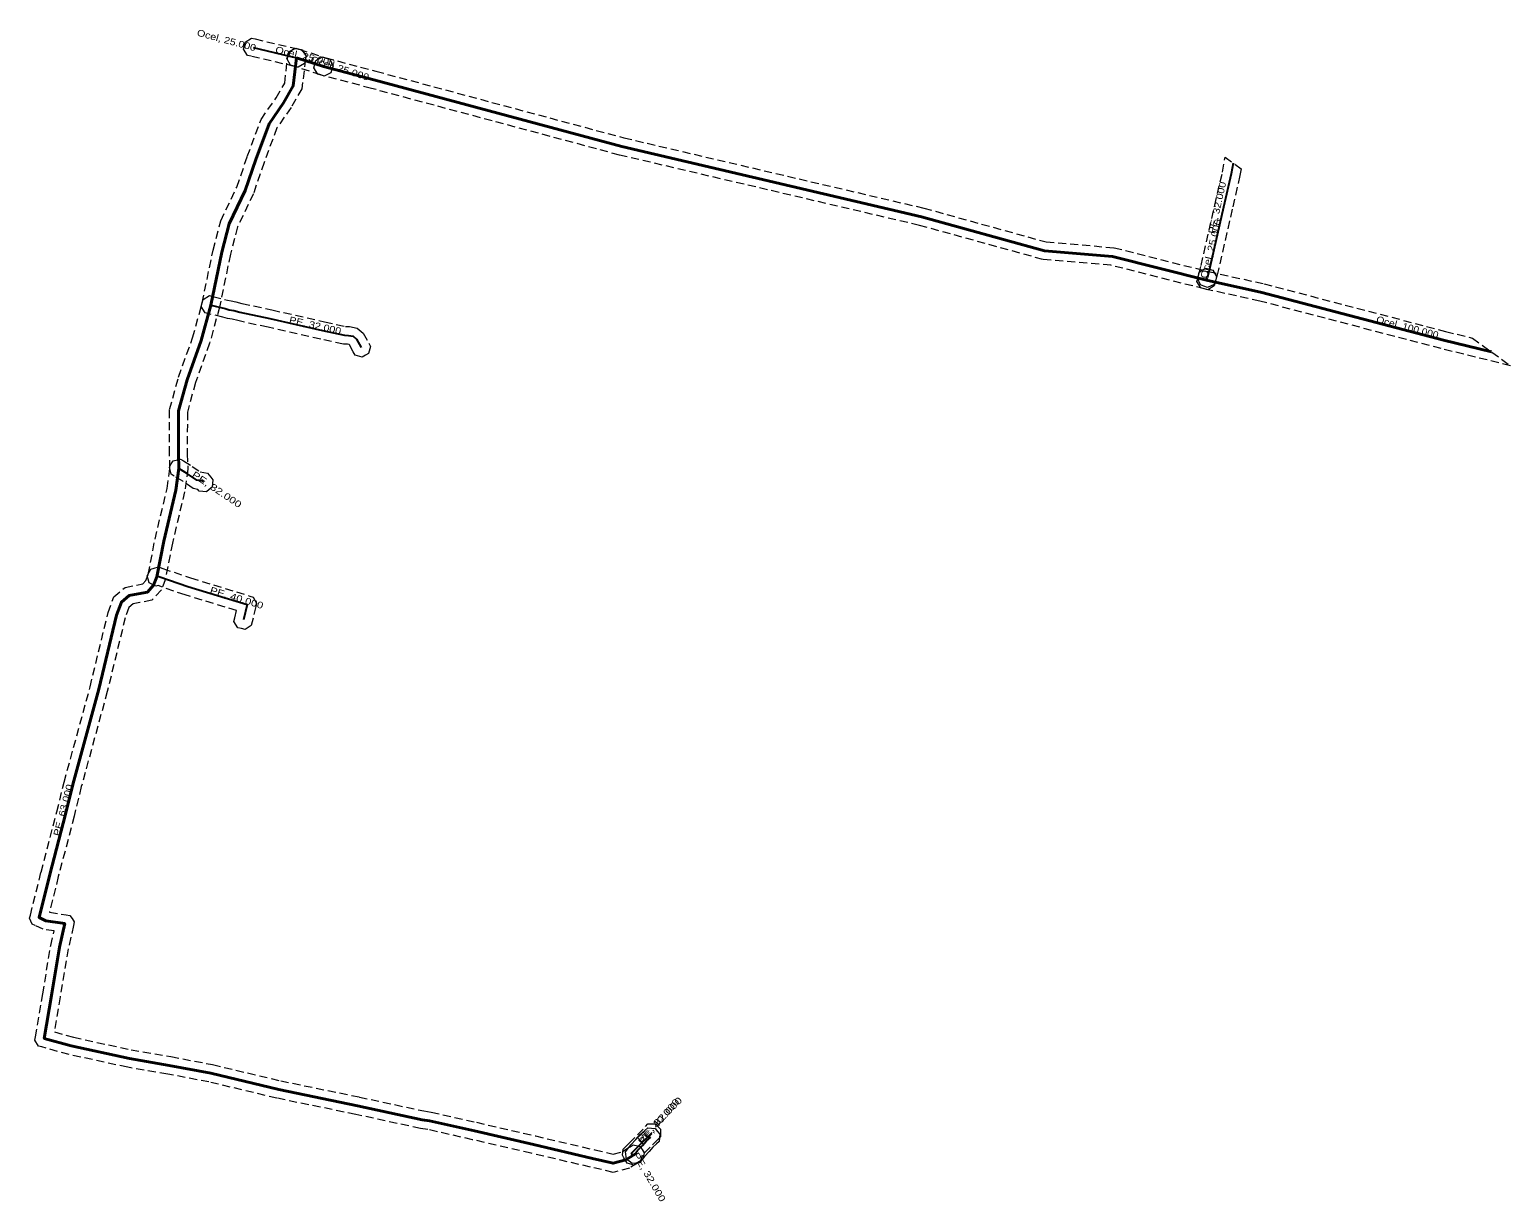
# Model space of a CAD drawing. Extents: x -640775 to -624586, y -1148563 to -1138811.
# Drawn here: x -625900 to -625733.5, y -1147350.6 to -1147218.8 of the extents above; entities that cross this region are included whole.
import ezdxf
from ezdxf.enums import TextEntityAlignment as Align

# ---------------------------------------------------------------- set-up
doc = ezdxf.new("R2010")
doc.units = 0
doc.header["$LTSCALE"] = 0.3
doc.linetypes.add('MEDIUM_DASHED', pattern=[4.5, 3, -1.5])
doc.layers.add('1', color=7, linetype='MEDIUM_DASHED', lineweight=13)
doc.layers.add('24', color=7, linetype='Continuous', lineweight=40)
doc.layers.add('30', color=7, linetype='Continuous')

msp = doc.modelspace()

# ---------------------------------------------------------------- linework, layer by layer
at = {"layer": '1'}
for points in [[(-625875.72, -1147220.24), (-625875.016, -1147219.802), (-625874.613, -1147219.896), (-625869.723, -1147221.036), (-625869.32, -1147221.13), (-625868.882, -1147221.834), (-625868.976, -1147222.237), (-625869.07, -1147222.64), (-625869.774, -1147223.078), (-625870.177, -1147222.984), (-625875.067, -1147221.844), (-625875.47, -1147221.75), (-625875.908, -1147221.046), (-625875.814, -1147220.643)], [(-625870.774, -1147221.308), (-625870.036, -1147220.931), (-625869.642, -1147221.059), (-625866.612, -1147222.039), (-625866.218, -1147222.166), (-625865.841, -1147222.904), (-625865.969, -1147223.298), (-625866.096, -1147223.692), (-625866.834, -1147224.069), (-625867.228, -1147223.941), (-625870.258, -1147222.961), (-625870.652, -1147222.834), (-625871.029, -1147222.096), (-625870.901, -1147221.702)], [(-625740.763, -1147252.771), (-625737.736, -1147253.519), (-625733.477, -1147256.63), (-625741.257, -1147254.709), (-625761.644, -1147249.362), (-625767.88, -1147247.993), (-625778.376, -1147245.339), (-625786.027, -1147244.689), (-625799.927, -1147240.849), (-625833.634, -1147232.95), (-625861.538, -1147225.456), (-625867.177, -1147223.956), (-625867.577, -1147223.85), (-625867.992, -1147223.133), (-625867.886, -1147222.733), (-625867.78, -1147222.333), (-625867.063, -1147221.918), (-625866.663, -1147222.024), (-625861.022, -1147223.524), (-625833.146, -1147231.01), (-625799.433, -1147238.911), (-625785.673, -1147242.711), (-625778.044, -1147243.361), (-625767.42, -1147246.047), (-625761.176, -1147247.418)], [(-625765.85, -1147234.861), (-625765.555, -1147233.189), (-625763.756, -1147234.503), (-625763.89, -1147235.259), (-625764.755, -1147239.033), (-625766.298, -1147245.827), (-625766.596, -1147246.963), (-625766.644, -1147247.091), (-625766.789, -1147247.479), (-625767.543, -1147247.821), (-625767.931, -1147247.676), (-625768.319, -1147247.531), (-625768.661, -1147246.777), (-625768.516, -1147246.389), (-625768.504, -1147246.357), (-625768.242, -1147245.353), (-625766.705, -1147238.587)], [(-625768.295, -1147247.89), (-625768.721, -1147247.179), (-625768.62, -1147246.777), (-625768.55, -1147246.497), (-625768.45, -1147246.095), (-625767.739, -1147245.669), (-625767.337, -1147245.77), (-625766.935, -1147245.87), (-625766.509, -1147246.581), (-625766.61, -1147246.983), (-625766.68, -1147247.263), (-625766.78, -1147247.665), (-625767.491, -1147248.091), (-625767.893, -1147247.99)], [(-625880.46, -1147249.167), (-625879.751, -1147248.74), (-625879.349, -1147248.84), (-625877.733, -1147249.241), (-625877.31, -1147249.351), (-625876.781, -1147249.441), (-625876.099, -1147249.617), (-625872.723, -1147250.354), (-625866.802, -1147251.694), (-625864.451, -1147252.212), (-625863.99, -1147252.222), (-625863.154, -1147252.389), (-625862.447, -1147252.982), (-625861.827, -1147254.093), (-625861.625, -1147254.455), (-625861.851, -1147255.251), (-625862.213, -1147255.453), (-625862.575, -1147255.655), (-625863.371, -1147255.429), (-625863.573, -1147255.067), (-625864.013, -1147254.278), (-625864.046, -1147254.251), (-625864.21, -1147254.218), (-625864.689, -1147254.208), (-625867.238, -1147253.646), (-625873.157, -1147252.306), (-625876.561, -1147251.563), (-625877.199, -1147251.399), (-625877.73, -1147251.309), (-625878.227, -1147251.179), (-625879.831, -1147250.78), (-625880.233, -1147250.68), (-625880.66, -1147249.971), (-625880.56, -1147249.569)], [(-625880.089, -1147270.81), (-625880.912, -1147270.719), (-625881.068, -1147270.524), (-625881.567, -1147270.418), (-625882.749, -1147269.622), (-625883.7, -1147269.044), (-625884.054, -1147268.829), (-625884.249, -1147268.024), (-625884.034, -1147267.67), (-625883.819, -1147267.316), (-625883.014, -1147267.121), (-625882.66, -1147267.336), (-625881.671, -1147267.938), (-625880.773, -1147268.542), (-625879.953, -1147268.716), (-625879.609, -1147269.145), (-625879.35, -1147269.469), (-625879.441, -1147270.292), (-625879.765, -1147270.551)], [(-625876.7, -1147284.153), (-625882.478, -1147282.392), (-625885.527, -1147281.35), (-625885.785, -1147281.426), (-625886.512, -1147281.03), (-625886.629, -1147280.632), (-625886.746, -1147280.235), (-625886.35, -1147279.508), (-625885.952, -1147279.391), (-625885.472, -1147279.249), (-625885.002, -1147279.415), (-625881.862, -1147280.488), (-625875.218, -1147282.513), (-625874.839, -1147282.629), (-625874.446, -1147283.316), (-625874.537, -1147283.701), (-625874.947, -1147285.431), (-625875.043, -1147285.834), (-625875.748, -1147286.269), (-625876.151, -1147286.173), (-625876.554, -1147286.077), (-625876.989, -1147285.372), (-625876.893, -1147284.969)], [(-625829.309, -1147343.563), (-625830.207, -1147344.471), (-625831.102, -1147345.385), (-625831.278, -1147346.055), (-625831.636, -1147346.264), (-625831.994, -1147346.473), (-625832.795, -1147346.262), (-625833.004, -1147345.904), (-625833.074, -1147345.784), (-625833.144, -1147345.664), (-625833.314, -1147345.372), (-625833.231, -1147344.702), (-625832.995, -1147344.461), (-625832.555, -1147344.011), (-625831.633, -1147343.069), (-625830.731, -1147342.157), (-625830.44, -1147341.862), (-625829.612, -1147341.858), (-625829.317, -1147342.149), (-625829.022, -1147342.44), (-625829.018, -1147343.268)], [(-625832.872, -1147345.803), (-625832.973, -1147344.981), (-625832.718, -1147344.655), (-625832.371, -1147344.21), (-625831.804, -1147343.602), (-625831.317, -1147343.039), (-625830.779, -1147342.58), (-625830.464, -1147342.311), (-625829.639, -1147342.376), (-625829.37, -1147342.691), (-625829.101, -1147343.006), (-625829.166, -1147343.831), (-625829.481, -1147344.1), (-625829.903, -1147344.461), (-625830.316, -1147344.938), (-625830.849, -1147345.51), (-625831.142, -1147345.885), (-625831.397, -1147346.212), (-625832.219, -1147346.313), (-625832.545, -1147346.058)]]:
    msp.add_lwpolyline(points, close=True, dxfattribs=at)
for points in [[(-625894.96, -1147307.265), (-625896.741, -1147314.057), (-625897.736, -1147318.062), (-625895.867, -1147318.352), (-625895.44, -1147318.418), (-625895.195, -1147318.775), (-625894.951, -1147319.131), (-625895.043, -1147319.554), (-625895.618, -1147322.18), (-625896.524, -1147327.575), (-625897.185, -1147331.519), (-625895.04, -1147332.119), (-625888.56, -1147333.518), (-625884.082, -1147334.286), (-625879.39, -1147335.182), (-625871.723, -1147337.014), (-625862.884, -1147338.832), (-625855.647, -1147340.397), (-625854.813, -1147340.527), (-625849.717, -1147341.675), (-625843.103, -1147343.206), (-625836.434, -1147344.766), (-625834.373, -1147345.241), (-625833.324, -1147344.971), (-625832.673, -1147344.554), (-625832.456, -1147344.42), (-625832.104, -1147344.202), (-625831.298, -1147344.392), (-625831.08, -1147344.744), (-625830.862, -1147345.096), (-625831.052, -1147345.902), (-625831.404, -1147346.12), (-625831.607, -1147346.246), (-625832.516, -1147346.829), (-625834.347, -1147347.299), (-625836.886, -1147346.714), (-625843.557, -1147345.154), (-625850.163, -1147343.625), (-625855.187, -1147342.493), (-625856.013, -1147342.363), (-625863.296, -1147340.788), (-625872.157, -1147338.966), (-625879.81, -1147337.138), (-625884.438, -1147336.254), (-625888.94, -1147335.482), (-625895.52, -1147334.061), (-625898.589, -1147333.203), (-625898.958, -1147333.1), (-625899.37, -1147332.453), (-625899.306, -1147332.075), (-625898.496, -1147327.245), (-625897.582, -1147321.8), (-625897.224, -1147320.165), (-625898.452, -1147319.975), (-625899.348, -1147319.539), (-625899.666, -1147319.384), (-625899.966, -1147318.743), (-625899.88, -1147318.399), (-625898.679, -1147313.563), (-625896.9, -1147306.775), (-625896.088, -1147303.44), (-625893.168, -1147292.74), (-625891.139, -1147284.382), (-625890.5, -1147282.61), (-625889.238, -1147281.539), (-625887.961, -1147281.288), (-625887.242, -1147281.15), (-625886.89, -1147280.768), (-625886.636, -1147280.08), (-625885.868, -1147276.138), (-625884.504, -1147270.424), (-625884.183, -1147268.138), (-625884.24, -1147266.557), (-625884.23, -1147261.564), (-625883.224, -1147257.908), (-625881.634, -1147253.488), (-625880.563, -1147249.577), (-625879.344, -1147243.632), (-625878.473, -1147240.333), (-625876.658, -1147236.542), (-625875.492, -1147233.115), (-625873.943, -1147228.953), (-625872.255, -1147226.524), (-625871.289, -1147224.849), (-625870.943, -1147221.894), (-625870.895, -1147221.482), (-625870.245, -1147220.969), (-625869.834, -1147221.017), (-625869.422, -1147221.065), (-625868.909, -1147221.715), (-625868.957, -1147222.126), (-625869.351, -1147225.491), (-625870.565, -1147227.596), (-625872.157, -1147229.887), (-625873.608, -1147233.785), (-625874.802, -1147237.298), (-625876.587, -1147241.027), (-625877.396, -1147244.088), (-625878.617, -1147250.043), (-625879.726, -1147254.092), (-625881.316, -1147258.512)], [(-625881.316, -1147258.512), (-625882.23, -1147261.836), (-625882.24, -1147266.523), (-625882.177, -1147268.242), (-625882.536, -1147270.796), (-625883.912, -1147276.562), (-625884.704, -1147280.62), (-625885.15, -1147281.832), (-625886.218, -1147282.99), (-625887.579, -1147283.252), (-625888.342, -1147283.401), (-625888.8, -1147283.79), (-625889.221, -1147284.958), (-625891.232, -1147293.24), (-625894.152, -1147303.94), (-625894.96, -1147307.265)]]:
    msp.add_lwpolyline(points, dxfattribs=at)
at = {"layer": '24', "lineweight": 25}
for p, q in [((-625874.84, -1147220.87), (-625869.95, -1147222.01)), ((-625767.65, -1147247.02), (-625767.58, -1147246.74))]:
    msp.add_line(p, q, dxfattribs=at)
at = {"layer": '24'}
msp.add_line((-625869.95, -1147222.01), (-625866.92, -1147222.99), dxfattribs=at)
for points in [[(-625869.95, -1147222.01), (-625870.32, -1147225.17), (-625871.41, -1147227.06), (-625873.05, -1147229.42), (-625874.55, -1147233.45), (-625875.73, -1147236.92), (-625877.53, -1147240.68), (-625878.37, -1147243.86), (-625879.59, -1147249.81)], [(-625866.92, -1147222.99), (-625861.28, -1147224.49), (-625833.39, -1147231.98), (-625799.68, -1147239.88), (-625785.85, -1147243.7), (-625778.21, -1147244.35), (-625767.65, -1147247.02)], [(-625767.65, -1147247.02), (-625761.41, -1147248.39), (-625741.01, -1147253.74), (-625735.608, -1147255.074)], [(-625879.59, -1147249.81), (-625880.68, -1147253.79), (-625882.27, -1147258.21), (-625883.23, -1147261.7), (-625883.24, -1147266.54), (-625883.18, -1147268.19)], [(-625883.18, -1147268.19), (-625883.52, -1147270.61), (-625884.89, -1147276.35), (-625885.67, -1147280.35)], [(-625885.67, -1147280.35), (-625886.02, -1147281.3), (-625886.73, -1147282.07), (-625887.77, -1147282.27), (-625888.79, -1147282.47), (-625889.65, -1147283.2), (-625890.18, -1147284.67), (-625892.2, -1147292.99), (-625895.12, -1147303.69), (-625895.93, -1147307.02), (-625897.71, -1147313.81), (-625898.91, -1147318.64), (-625898.15, -1147319.01), (-625896.02, -1147319.34), (-625896.6, -1147321.99), (-625897.51, -1147327.41), (-625898.32, -1147332.24), (-625895.28, -1147333.09), (-625888.75, -1147334.5), (-625884.26, -1147335.27), (-625879.6, -1147336.16), (-625871.94, -1147337.99), (-625863.09, -1147339.81), (-625855.83, -1147341.38), (-625855, -1147341.51), (-625849.94, -1147342.65), (-625843.33, -1147344.18), (-625836.66, -1147345.74), (-625834.36, -1147346.27), (-625832.92, -1147345.9), (-625832.14, -1147345.4), (-625831.93, -1147345.27)]]:
    msp.add_lwpolyline(points, dxfattribs=at)
at = {"layer": '24', "lineweight": 25}
for points in [[(-625764.656, -1147233.847), (-625764.87, -1147235.06), (-625765.73, -1147238.81), (-625767.27, -1147245.59), (-625767.47, -1147246.36)], [(-625767.47, -1147246.36), (-625767.55, -1147246.66), (-625767.58, -1147246.74)], [(-625879.59, -1147249.81), (-625877.98, -1147250.21), (-625877.52, -1147250.33), (-625876.99, -1147250.42), (-625876.33, -1147250.59), (-625872.94, -1147251.33), (-625867.02, -1147252.67), (-625864.57, -1147253.21), (-625864.1, -1147253.22), (-625863.6, -1147253.32), (-625863.23, -1147253.63), (-625862.7, -1147254.58)], [(-625880.39, -1147269.77), (-625880.51, -1147269.62), (-625881.17, -1147269.48), (-625882.21, -1147268.78), (-625883.18, -1147268.19)], [(-625885.67, -1147280.35), (-625885.5, -1147280.3), (-625885.33, -1147280.36), (-625882.17, -1147281.44), (-625875.51, -1147283.47), (-625875.92, -1147285.2)], [(-625832.14, -1147345.4), (-625832.21, -1147345.28), (-625832.28, -1147345.16), (-625831.84, -1147344.71), (-625830.92, -1147343.77), (-625830.02, -1147342.86)], [(-625831.93, -1147345.27), (-625831.61, -1147344.86), (-625831.06, -1147344.27), (-625830.61, -1147343.75), (-625830.13, -1147343.34)]]:
    msp.add_lwpolyline(points, dxfattribs=at)

# ---------------------------------------------------------------- texts
at = {"layer": '30', "width": 1.2}
for s, rotation, p in [('Ocel, 25.000', 344.921, (-625877.92, -1147220.399)), ('PE, 32.000', 77.349, (-625766.076, -1147238.95))]:
    msp.add_text(s, height=0.75, rotation=rotation, dxfattribs=at).set_placement(p, align=Align.CENTER)
at = {"layer": '30'}
for s, rotation, width, p in [('Ocel, 25.000', 346.877, 1.2, (-625872.395, -1147221.44)), ('Ocel, 25.000', 342.077, 1.2, (-625868.435, -1147222.5)), ('Ocel, 25.000', 75.964, 1.2, (-625767.615, -1147246.88)), ('PE, 32.000', 347.246, 1.2, (-625870.84, -1147251.805)), ('Ocel, 100.000', 345.305, 1.15, (-625748.618, -1147251.745)), ('PE, 32.000', 326.056, 1.3, (-625881.801, -1147269.055)), ('PE, 40.000', 343.049, 1.25, (-625879.758, -1147282.175)), ('PE, 63.000', 75.355, 1.2, (-625896.595, -1147309.556)), ('PE, 32.000', 45.616, 1.35, (-625831.201, -1147344.057)), ('PE, 40.000', 49.004, 1.3, (-625831.063, -1147344.273)), ('PE, 32.000', 300.256, 1.25, (-625832.175, -1147345.34))]:
    msp.add_text(s, height=0.75, rotation=rotation, dxfattribs=dict(at, width=width)).set_placement(p)

doc.saveas('drawing.dxf')
